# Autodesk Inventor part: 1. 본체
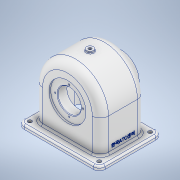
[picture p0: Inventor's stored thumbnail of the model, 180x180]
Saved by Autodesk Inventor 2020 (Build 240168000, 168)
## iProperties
Created: 2022-09
Part Number: 1. 본체
Material: 알루미늄 6061
Document SubType Name: Modeling
Designer: Administrator
Density: 2.7 g/cm^3
Appearance: 알루미늄 - 평지
Mass: 785.035 g
Surface Area: 1042.06 cm^2
Volume: 290.754 cm^3
Author: Administrator
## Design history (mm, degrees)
sketch "스케치2" dims "d0" = 114
  geometry: L1 (-57, 64)-(57, 64); L2 (57, 64)-(57, 0); L3 (57, 0)-(-57, 0); L4 (-57, 0)-(-57, 64); 4 further points
  constraints: 8 end point, 2 parallel, 2 vertical, 1 horizontal, 1 horizontal alignment, 1 midpoint, 1 perpendicular, 3 other
  dimensions: "d1" = 64 distance of point (0, 64) point (0, 0); "d18" = 64 distance between parallel lines of L1 L3
extrude "돌출1" new body sketch "스케치2" distance "d2" = 78; taper "d3" = 0 deg
fillet "모깎기1" dims "d4" = 14
feature "쉘1" dims "d5" = 5
sketch "스케치3"
  geometry: L1 (-70, 15)-(70, 15); L2 (70, 15)-(70, -93); L3 (70, -93)-(-70, -93); L4 (-70, -93)-(-70, 15); L5 (-57, -14)-(-57, -64) reference; L6 (43, 0)-(-43, 0) reference; L7 (43, 0)-(-43, 0) reference; L8 (57, -14)-(57, -64) reference; L9 (57, -14)-(57, -64) reference; L10 (43, -78)-(-43, -78) reference; A1 r 14 centre (-43, -14) between (-43, 0) and (-57, -14) reference; A2 r 14 centre (-43, -14) between (-43, 0) and (-57, -14) reference; A3 r 14 centre (43, -14) between (57, -14) and (43, 0) reference; A4 r 14 centre (43, -14) between (57, -14) and (43, 0) reference; A5 r 14 centre (43, -64) between (43, -78) and (57, -64) reference; A6 r 14 centre (-43, -64) between (-57, -64) and (-43, -78) reference; 8 further points
  constraints: 8 end point, 3 midpoint, 2 parallel, 1 horizontal, 1 horizontal alignment, 1 perpendicular, 1 vertical alignment
  dimensions: "d6" = 108 distance of L3.end L1.start; "d7" = 140 distance of L1.start L1.end
extrude "돌출2" join sketch "스케치3" distance "d8" = 7; taper "d9" = 0 deg
fillet "모깎기2" dims "d10" = 10
sketch "스케치5"
  geometry: A1 r 10 centre (-60, 83) between (-60, 93) and (-70, 83) reference; A2 r 10 centre (-60, -5) between (-70, -5) and (-60, -15) reference; A3 r 10 centre (60, -5) between (60, -15) and (70, -5) reference; A4 r 10 centre (60, 83) between (70, 83) and (60, 93) reference; 5 further points
  constraints: 4 coincident
hole "구멍1" sketch "스케치5" at (-60, 83), (-60, -5), (60, -5), (60, 83) diameter "d11" = 6.6; stored, may be unused: countersink angle "d15" = 90 deg, drill point angle "d17" = 118 deg; dims "d12" = 6, "d13" = 4, "d14" = 2, "d16" = 8
node "작업 평면1"
sketch "스케치6"
  geometry: L1 (3, 79)-(3, 29) reference; C1 r 6 at (60, 54); 2 further points
  constraints: 1 centre point, 1 horizontal alignment, 1 midpoint, 1 vertical alignment
  dimensions: "d20" = 12 diameter of C1
extrude "돌출3" join sketch "스케치6" stored distance "d21" = 7; taper "d22" = 0 deg
sketch "스케치7"
  geometry: C1 r 6 at (0, 0) reference; 2 further points
  constraints: 1 coincident
hole "구멍2" sketch "스케치7" at (0, 0) diameter "d23" = 5.1881; stored, may be unused: countersink angle "d27" = 90 deg, drill point angle "d29" = 118 deg; dims "d24" = 12, "d25" = 4, "d26" = 2, "d28" = 16
sketch "스케치8"
  geometry: A1 r 43 centre (0, 64) between (43, 64) and (-43, 64) reference; 2 further points
  constraints: 1 coincident
hole "구멍3" sketch "스케치8" at (0, 64) diameter "d30" = 64; stored, may be unused: countersink angle "d34" = 90 deg, drill point angle "d36" = 0 deg; dims "d31" = 12, "d32" = 4, "d33" = 2, "d35" = 3
sketch "스케치9"
  geometry: C1 r 31 at (0, 64); A1 r 43 centre (0, 64) between (43, 64) and (-43, 64) reference; 1 further point
  constraints: 1 centre point, 1 coincident
  dimensions: "d37" = 62 diameter of C1
extrude "돌출4" join sketch "스케치9" distance "d38" = 15; taper "d39" = 0 deg
sketch "스케치10"
  geometry: C1 r 31 at (0, 0) reference; 2 further points
  constraints: 1 coincident
hole "구멍4" sketch "스케치10" at (0, 0) diameter "d40" = 40; stored, may be unused: countersink angle "d44" = 90 deg, drill point angle "d46" = 0 deg; dims "d41" = 12, "d42" = 4, "d43" = 2, "d45" = 16
sketch "스케치11"
  geometry: C1 r 20 at (0, 0) reference; 2 further points
  constraints: 1 coincident
hole "구멍5" sketch "스케치11" at (0, 0) diameter "d47" = 35; stored, may be unused: countersink angle "d51" = 90 deg, drill point angle "d53" = 0 deg; dims "d48" = 12, "d49" = 4, "d50" = 2, "d52" = 16
sketch "스케치12"
  geometry: C1 r 31 at (0, 0) reference; A1 r 24 centre (0, 0) between (0, 24) and (-24, 0); 3 further points
  constraints: 4 point on circle, 1 centre point, 1 coincident
  dimensions: "d54" = 48 diameter of A1
hole "구멍6" sketch "스케치12" at (0, 24), (-24, 0), (0, -24), (24, 0) diameter "d55" = 2.459; stored, may be unused: countersink angle "d59" = 90 deg, drill point angle "d61" = 118 deg; dims "d56" = 7, "d57" = 4, "d58" = 2, "d60" = 9
node "작업 평면2"
node "작업 평면3"
sketch "스케치13"
  geometry: C1 r 28 at (0, 0); A1 r 43 centre (0, 0) between (43, 0) and (-43, 0) reference; 1 further point
  constraints: 1 centre point, 1 coincident, 1 vertical alignment
  dimensions: "d63" = 56 diameter of C1
extrude "돌출5" join sketch "스케치13" stored distance "d64" = 15; taper "d65" = 30 deg
sketch "스케치14"
  geometry: C1 r 32 at (0, 0) reference; 2 further points
  constraints: 1 coincident
hole "구멍7" sketch "스케치14" at (0, 0) diameter "d66" = 40; stored, may be unused: countersink angle "d70" = 90 deg, drill point angle "d72" = 0 deg; dims "d67" = 7, "d68" = 4, "d69" = 2, "d71" = 9
fillet "모깎기3" dims "d73" = 3, "d74" = 1, "d75" = 0.6
chamfer "모따기1" distance "d76" = 1; stored, may be unused: second distance "d77" = 2, angle "d78" = 45 deg
sketch "스케치15"
  geometry: L1 (-19, -64)-(69, -64) reference; L2 (-29, -60)-(-29, -64) reference; L3 (-14, 0)-(-14, -54) reference; L4 (5.304, -41.167)-(44.696, -41.167); L5 (44.696, -41.167)-(44.696, -52.833); L6 (44.696, -52.833)-(5.304, -52.833); L7 (5.304, -52.833)-(5.304, -41.167); 1 further point
  constraints: 2 other
feature "엠보싱1" sketch "스케치15" dims "d6" = 108, "d7" = 140, "d82" = 0.5, "d83" = 0
node "솔리드1"
mirror "미러1"
node "투영된 루프1"
node "투영된 루프2"
node "투영된 루프3"
node "투영된 루프4"
feature "A9D066F2-1C7D-4E18-AEED-F7BC21143FA4" dims "d11" = 6.6, "d12" = 6, "d13" = 4, "d14" = 2, "d15" = 90 deg, "d16" = 8, "d17" = 118 deg
other parameters: "d19" = -124, "d62" = 14
